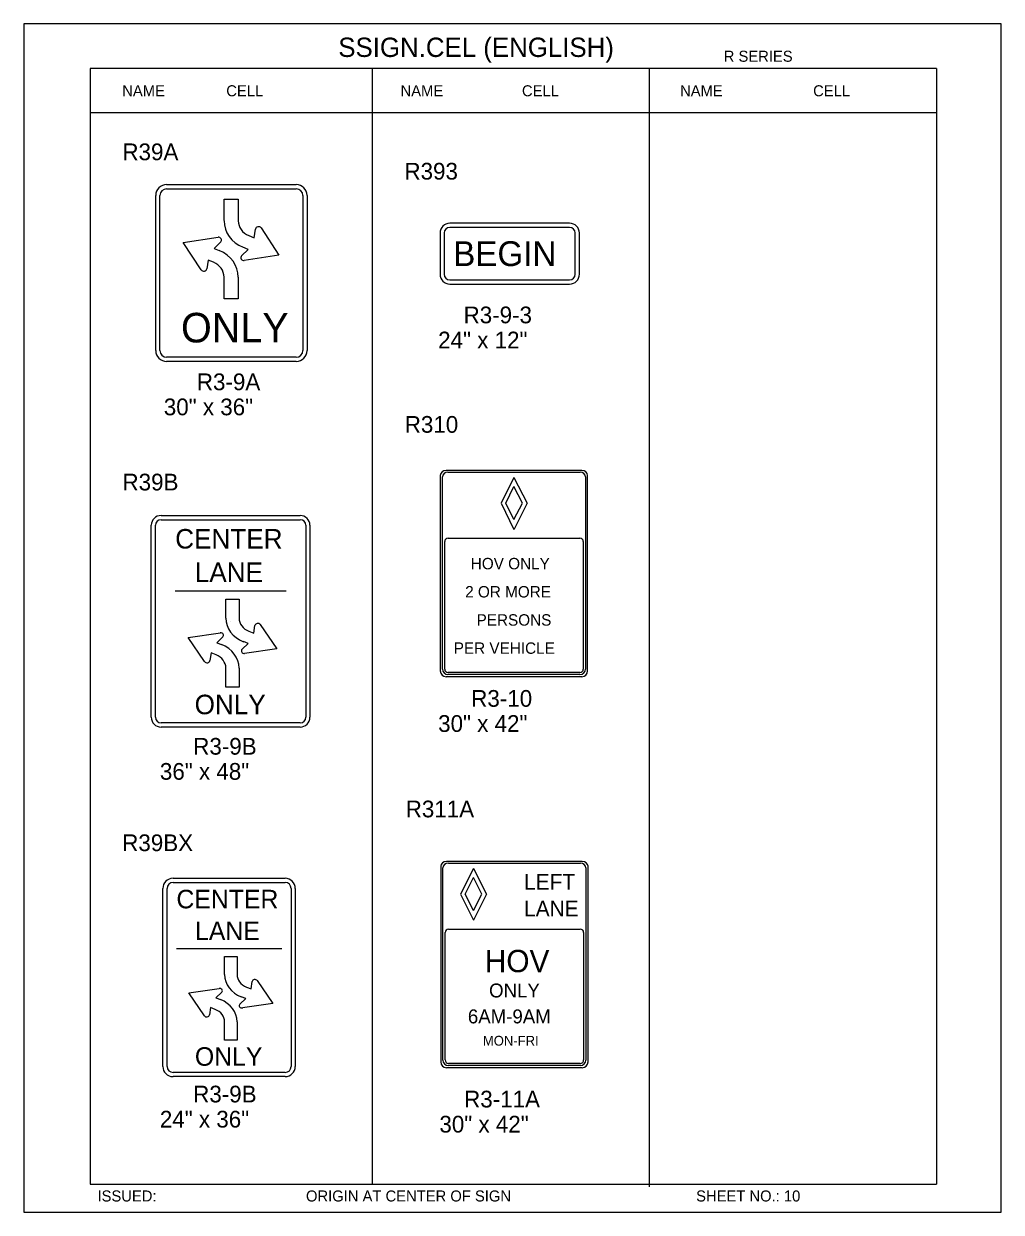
# Model space of a CAD drawing. Extents: x -5299 to 22597, y -19549 to -1808.
# Drawn here: x -2827 to -2126, y -4545 to -3692 of the extents above; entities that cross this region are included whole.
import ezdxf

# ---------------------------------------------------------------- set-up
doc = ezdxf.new("R2010")
doc.units = 0
for name, color, linetype in [('Level 1', 7, 'Continuous'), ('Level 2', 7, 'Continuous'), ('Level 3', 7, 'Continuous'), ('Level 63', 7, 'Continuous')]:
    doc.layers.add(name, color=color, linetype=linetype)

msp = doc.modelspace()

# ---------------------------------------------------------------- linework, layer by layer
at = {"layer": 'Level 1'}
for p, q in [((-2172.62, -3724.36), (-2779.63, -3724.36)), ((-2779.63, -3724.36), (-2779.63, -4524.36)), ((-2577.29, -3724.36), (-2577.29, -4524.36)), ((-2378.55, -3724.36), (-2378.55, -4524.36)), ((-2172.62, -3724.36), (-2172.62, -4524.36)), ((-2378.55, -3726.39), (-2378.55, -4526.39)), ((-2172.62, -3756.03), (-2779.63, -3756.03)), ((-2729.49, -3926.55), (-2729.49, -3815.35)), ((-2724.69, -3810.55), (-2631.77, -3810.55)), ((-2683.49, -3833.38), (-2683.49, -3817.93)), ((-2683.49, -3817.93), (-2673.31, -3817.93)), ((-2673.31, -3817.93), (-2673.31, -3833.44)), ((-2626.97, -3815.35), (-2626.97, -3926.55)), ((-2665.74, -3844.1), (-2661.9, -3845.68)), ((-2661.9, -3845.68), (-2660.98, -3839.41)), ((-2656.87, -3838.59), (-2644.09, -3858.2)), ((-2525.59, -3842.23), (-2525.59, -3871.85)), ((-2435.68, -3838.23), (-2521.59, -3838.23)), ((-2431.68, -3871.85), (-2431.68, -3842.23)), ((-2712.71, -3849.08), (-2687.79, -3845.27)), ((-2699.92, -3868.69), (-2712.71, -3849.08)), ((-2685.83, -3848.61), (-2690.6, -3853.29)), ((-2666.2, -3853.99), (-2669.92, -3852.47)), ((-2690.6, -3853.29), (-2686.88, -3854.81)), ((-2670.96, -3858.67), (-2666.2, -3853.99)), ((-2644.09, -3858.2), (-2669.01, -3862.01)), ((-2478.63, -3857.04), (-2478.63, -3857.04)), ((-2694.9, -3861.6), (-2695.81, -3867.87)), ((-2691.05, -3863.18), (-2694.9, -3861.6)), ((-2683.49, -3889.35), (-2683.49, -3873.84)), ((-2678.23, -3870.95), (-2678.23, -3870.95)), ((-2673.31, -3873.89), (-2673.31, -3889.35)), ((-2521.59, -3875.85), (-2435.68, -3875.85)), ((-2673.31, -3889.35), (-2683.49, -3889.35)), ((-2631.77, -3931.35), (-2724.69, -3931.35)), ((-2522.9, -4013.86), (-2428.2, -4013.86)), ((-2526.81, -4155), (-2526.81, -4017.07)), ((-2424.29, -4017.07), (-2424.29, -4155)), ((-2728.68, -4047.84), (-2628.88, -4047.84)), ((-2732.68, -4189.57), (-2732.68, -4051.84)), ((-2624.88, -4051.84), (-2624.88, -4189.57)), ((-2525.24, -4154.96), (-2525.24, -4063.57)), ((-2522.84, -4061.17), (-2428.26, -4061.17)), ((-2425.86, -4063.57), (-2425.86, -4154.96)), ((-2475.55, -4073.37), (-2475.55, -4073.37)), ((-2475.55, -4073.37), (-2475.55, -4073.37)), ((-2718.58, -4098.91), (-2639.01, -4098.91)), ((-2682.17, -4118.45), (-2682.17, -4104.78)), ((-2682.17, -4104.78), (-2672.75, -4104.78)), ((-2672.75, -4104.78), (-2672.75, -4118.5)), ((-2678.78, -4120.71), (-2678.78, -4120.71)), ((-2662.18, -4129.32), (-2661.34, -4123.78)), ((-2657.53, -4123.05), (-2645.69, -4140.4)), ((-2709.23, -4132.32), (-2686.16, -4128.96)), ((-2697.4, -4149.66), (-2709.23, -4132.32)), ((-2684.35, -4131.91), (-2688.76, -4136.05)), ((-2665.75, -4127.92), (-2662.18, -4129.32)), ((-2688.76, -4136.05), (-2685.32, -4137.4)), ((-2670.58, -4140.81), (-2666.17, -4136.67)), ((-2666.17, -4136.67), (-2669.61, -4135.32)), ((-2645.69, -4140.4), (-2668.76, -4143.76)), ((-2692.74, -4143.4), (-2693.59, -4148.94)), ((-2689.18, -4144.8), (-2692.74, -4143.4)), ((-2682.17, -4167.94), (-2682.17, -4154.22)), ((-2672.75, -4154.27), (-2672.75, -4167.94)), ((-2428.21, -4158.92), (-2522.89, -4158.92)), ((-2428.26, -4157.36), (-2522.84, -4157.36)), ((-2672.75, -4167.94), (-2682.17, -4167.94)), ((-2628.88, -4193.57), (-2728.68, -4193.57)), ((-2522.63, -4294.26), (-2427.92, -4294.26)), ((-2526.54, -4435.41), (-2526.54, -4297.48)), ((-2424.01, -4297.48), (-2424.01, -4435.41)), ((-2724.41, -4439.97), (-2724.41, -4312.35)), ((-2720.09, -4308.03), (-2639.7, -4308.03)), ((-2635.38, -4312.35), (-2635.38, -4439.97)), ((-2524.97, -4435.36), (-2524.97, -4343.98)), ((-2522.57, -4341.58), (-2427.98, -4341.58)), ((-2425.58, -4343.98), (-2425.58, -4435.36)), ((-2717.7, -4355.46), (-2642.11, -4355.46)), ((-2683.12, -4374.02), (-2683.12, -4361.03)), ((-2683.12, -4361.03), (-2674.16, -4361.03)), ((-2674.16, -4361.03), (-2674.16, -4374.07)), ((-2475.27, -4366.94), (-2475.27, -4366.94)), ((-2679.89, -4376.16), (-2679.89, -4376.16)), ((-2664.12, -4384.34), (-2663.32, -4379.08)), ((-2659.7, -4378.39), (-2648.46, -4394.87)), ((-2708.82, -4387.2), (-2686.9, -4384)), ((-2697.58, -4403.67), (-2708.82, -4387.2)), ((-2685.18, -4386.81), (-2689.37, -4390.74)), ((-2667.51, -4383.02), (-2664.12, -4384.34)), ((-2693.16, -4397.72), (-2693.96, -4402.99)), ((-2689.77, -4399.05), (-2693.16, -4397.72)), ((-2689.37, -4390.74), (-2686.1, -4392.02)), ((-2672.1, -4395.26), (-2667.91, -4391.33)), ((-2667.91, -4391.33), (-2671.18, -4390.05)), ((-2648.46, -4394.87), (-2670.38, -4398.06)), ((-2683.12, -4421.03), (-2683.12, -4408)), ((-2674.16, -4408.05), (-2674.16, -4421.03)), ((-2674.16, -4421.03), (-2683.12, -4421.03)), ((-2427.93, -4439.33), (-2522.62, -4439.33)), ((-2427.98, -4437.76), (-2522.57, -4437.76)), ((-2639.7, -4444.29), (-2720.09, -4444.29)), ((-2779.63, -4524.36), (-2172.62, -4524.36))]:
    msp.add_line(p, q, dxfattribs=at)
for centre, radius, start, end in [((-2724.69, -3815.35), 4.8, 90, 180), ((-2631.77, -3815.35), 4.8, 0, 90), ((-2521.59, -3842.23), 4, 90, 180), ((-2435.68, -3842.23), 4, 0, 90), ((-2521.59, -3871.85), 4, 180, 270), ((-2435.68, -3871.85), 4, 270, 0), ((-2724.69, -3926.55), 4.8, 180, 270), ((-2631.77, -3926.55), 4.8, 270, 0), ((-2728.68, -4051.84), 4, 90, 180), ((-2628.88, -4051.84), 4, 0, 90), ((-2522.84, -4063.57), 2.4, 90, 180), ((-2428.26, -4063.57), 2.4, 0, 90), ((-2522.89, -4155), 3.92, 180, 270), ((-2522.84, -4154.96), 2.4, 180, 270), ((-2428.26, -4154.96), 2.4, 270, 0), ((-2428.21, -4155), 3.92, 270, 0), ((-2728.68, -4189.57), 4, 180, 270), ((-2628.88, -4189.57), 4, 270, 0), ((-2720.09, -4312.35), 4.32, 90, 180), ((-2639.7, -4312.35), 4.32, 0, 90), ((-2522.57, -4343.98), 2.4, 90, 180), ((-2427.98, -4343.98), 2.4, 0, 90), ((-2720.09, -4439.97), 4.32, 180, 270), ((-2639.7, -4439.97), 4.32, 270, 0), ((-2522.62, -4435.41), 3.92, 180, 270), ((-2522.57, -4435.36), 2.4, 180, 270), ((-2427.98, -4435.36), 2.4, 270, 0), ((-2427.93, -4435.41), 3.92, 270, 0)]:
    msp.add_arc(centre, radius, start, end, dxfattribs=at)
for centre, major_axis, ratio, start_param, end_param in [((-2660.13, -3833.42), (-23.38, 0), 0.8975, 6.282849, 7.423415), ((-2660.1, -3833.39), (13.19, 0), 0.8975, 3.143205, 4.271453), ((-2658.74, -3839.73), (-2.26, 0), 0.8975, 3.720842, 6.1394), ((-2687.54, -3847.26), (2.25, 0), 0.8975, 5.561964, 7.978205), ((-2696.67, -3873.86), (23.38, 0), 0.8975, 6.282849, 7.423415), ((-2669.26, -3860.02), (-2.25, 0), 0.8975, 5.561964, 7.978205), ((-2698.05, -3867.55), (2.26, 0), 0.8975, 3.720842, 6.1394), ((-2696.7, -3873.89), (-13.19, 0), 0.8975, 3.143205, 4.271453), ((-2522.9, -4017.07), (-3.91, 0), 0.822115, 4.712389, 6.283185), ((-2428.2, -4017.07), (-3.91, 0), 0.822115, 3.141593, 4.712389), ((-2660.55, -4118.48), (-21.65, 0), 0.857082, 6.282849, 7.423415), ((-2660.52, -4118.45), (12.21, 0), 0.857082, 3.143205, 4.271453), ((-2659.26, -4124.06), (-2.09, 0), 0.857082, 3.720842, 6.1394), ((-2685.93, -4130.72), (2.09, 0), 0.857082, 5.561964, 7.978205), ((-2694.38, -4154.24), (21.65, 0), 0.857082, 6.282849, 7.423415), ((-2669, -4142), (-2.09, 0), 0.857082, 5.561964, 7.978205), ((-2695.66, -4148.66), (2.09, 0), 0.857082, 3.720842, 6.1394), ((-2694.41, -4154.27), (-12.21, 0), 0.857082, 3.143205, 4.271453), ((-2522.63, -4297.48), (-3.91, 0), 0.822115, 4.712389, 6.283185), ((-2427.92, -4297.48), (-3.91, 0), 0.822115, 3.141593, 4.712389), ((-2662.57, -4374.04), (-20.57, 0), 0.857082, 6.282849, 7.423415), ((-2662.54, -4374.02), (11.6, 0), 0.857082, 3.143205, 4.271453), ((-2661.35, -4379.35), (-1.99, 0), 0.857082, 3.720842, 6.1394), ((-2686.68, -4385.67), (1.98, 0), 0.857082, 5.561964, 7.978205), ((-2694.71, -4408.02), (20.57, 0), 0.857082, 6.282849, 7.423415), ((-2670.6, -4396.39), (-1.98, 0), 0.857082, 5.561964, 7.978205), ((-2695.93, -4402.72), (1.99, 0), 0.857082, 3.720842, 6.1394), ((-2694.74, -4408.05), (-11.6, 0), 0.857082, 3.143205, 4.271453)]:
    msp.add_ellipse(centre, major_axis=major_axis, ratio=ratio, start_param=start_param, end_param=end_param, dxfattribs=at)
at = {"layer": 'Level 3'}
for p, q in [((-2724.69, -3807.55), (-2631.77, -3807.55)), ((-2732.49, -3926.55), (-2732.49, -3815.35)), ((-2623.97, -3815.35), (-2623.97, -3926.55)), ((-2435.68, -3835.23), (-2521.59, -3835.23)), ((-2528.59, -3842.23), (-2528.59, -3871.85)), ((-2428.68, -3871.85), (-2428.68, -3842.23)), ((-2521.59, -3878.85), (-2435.68, -3878.85)), ((-2631.77, -3934.35), (-2724.69, -3934.35)), ((-2426.95, -4012.57), (-2524.15, -4012.57)), ((-2528.38, -4016.04), (-2528.38, -4156.29)), ((-2475.55, -4017.6), (-2484.74, -4035.98)), ((-2475.55, -4017.6), (-2466.14, -4035.98)), ((-2422.72, -4156.29), (-2422.72, -4016.04)), ((-2481.45, -4035.98), (-2475.55, -4024.16)), ((-2469.42, -4035.98), (-2475.55, -4024.16)), ((-2484.74, -4035.98), (-2475.55, -4054.79)), ((-2475.55, -4047.79), (-2481.45, -4035.98)), ((-2475.55, -4047.79), (-2469.42, -4035.98)), ((-2466.12, -4036.01), (-2475.47, -4054.69)), ((-2728.68, -4044.84), (-2628.88, -4044.84)), ((-2735.68, -4189.57), (-2735.68, -4051.84)), ((-2621.88, -4051.84), (-2621.88, -4189.57)), ((-2426.92, -4160.49), (-2524.18, -4160.49)), ((-2628.88, -4196.57), (-2728.68, -4196.57)), ((-2426.67, -4292.97), (-2523.88, -4292.97)), ((-2528.1, -4296.45), (-2528.1, -4436.7)), ((-2504.64, -4298.01), (-2513.83, -4316.38)), ((-2504.64, -4298.01), (-2495.23, -4316.38)), ((-2422.44, -4436.7), (-2422.44, -4296.45)), ((-2727.41, -4439.97), (-2727.41, -4312.35)), ((-2720.09, -4305.03), (-2639.7, -4305.03)), ((-2632.38, -4312.35), (-2632.38, -4439.97)), ((-2510.54, -4316.38), (-2504.64, -4304.57)), ((-2498.52, -4316.38), (-2504.64, -4304.57)), ((-2513.83, -4316.38), (-2504.64, -4335.19)), ((-2504.64, -4328.19), (-2510.54, -4316.38)), ((-2504.64, -4328.19), (-2498.52, -4316.38)), ((-2495.22, -4316.42), (-2504.56, -4335.1)), ((-2639.7, -4447.29), (-2720.09, -4447.29)), ((-2426.64, -4440.9), (-2523.9, -4440.9))]:
    msp.add_line(p, q, dxfattribs=at)
for centre, radius, start, end in [((-2724.69, -3815.35), 7.8, 90, 180), ((-2631.77, -3815.35), 7.8, 0, 90), ((-2521.59, -3842.23), 7, 90, 180), ((-2435.68, -3842.23), 7, 0, 90), ((-2521.59, -3871.85), 7, 180, 270), ((-2435.68, -3871.85), 7, 270, 0), ((-2724.69, -3926.55), 7.8, 180, 270), ((-2631.77, -3926.55), 7.8, 270, 0), ((-2728.68, -4051.84), 7, 90, 180), ((-2628.88, -4051.84), 7, 0, 90), ((-2524.18, -4156.29), 4.2, 180, 270), ((-2426.92, -4156.29), 4.2, 270, 0), ((-2728.68, -4189.57), 7, 180, 270), ((-2628.88, -4189.57), 7, 270, 0), ((-2720.09, -4312.35), 7.32, 90, 180), ((-2639.7, -4312.35), 7.32, 0, 90), ((-2720.09, -4439.97), 7.32, 180, 270), ((-2639.7, -4439.97), 7.32, 270, 0), ((-2523.9, -4436.7), 4.2, 180, 270), ((-2426.64, -4436.7), 4.2, 270, 0)]:
    msp.add_arc(centre, radius, start, end, dxfattribs=at)
for centre, start_param, end_param in [((-2524.15, -4016.04), 4.712389, 6.283185), ((-2426.95, -4016.04), 3.141593, 4.712389), ((-2523.88, -4296.45), 4.712389, 6.283185), ((-2426.67, -4296.45), 3.141593, 4.712389)]:
    msp.add_ellipse(centre, major_axis=(-4.23, 0), ratio=0.822115, start_param=start_param, end_param=end_param, dxfattribs=at)
at = {"layer": 'Level 63'}
msp.add_lwpolyline([(-2827.14, -4544.55), (-2126.09, -4544.55), (-2126.09, -3692.17), (-2827.14, -3692.17)], close=True, dxfattribs=at)

# ---------------------------------------------------------------- texts
at = {"layer": 'Level 1'}
for s, height, p in [('BEGIN', 17.779, (-2519.14, -3865.93)), ('ONLY', 21.2, (-2714.35, -3920.71)), ('CENTER', 14, (-2718.53, -4068.54)), ('LANE', 14, (-2704.47, -4092.54)), ('HOV ONLY', 8.2, (-2506.54, -4083.45)), ('2 OR MORE', 8.2, (-2510.57, -4103.65)), ('PERSONS', 8.2, (-2502.37, -4123.85)), ('PER VEHICLE', 8.2, (-2518.77, -4144.05)), ('ONLY', 14, (-2704.58, -4187.38)), ('CENTER', 13.3, (-2717.65, -4326.6)), ('LANE', 13.3, (-2704.3, -4349.4)), ('HOV', 16, (-2496.5, -4372.38)), ('ONLY', 10, (-2493.42, -4390.5)), ('6AM-9AM', 10, (-2508.62, -4409.1)), ('MON-FRI', 7, (-2497.87, -4425.04)), ('ONLY', 13.3, (-2704.4, -4439.5))]:
    msp.add_text(s, height=height, dxfattribs=at).set_placement(p)
at = {"layer": 'Level 2'}
for s, p in [('R39A', (-2756.39, -3790.02)), ('R393', (-2554.12, -3803.91)), ('R310', (-2553.89, -3985.51)), ('R39B', (-2756.33, -4026.87)), ('R311A', (-2553.2, -4261.32)), ('R39BX', (-2756.53, -4285.57))]:
    msp.add_text(s, height=12, dxfattribs=at).set_placement(p)
at = {"layer": 'Level 3'}
for s, height, p in [('SSIGN.CEL (ENGLISH)', 13.8566, (-2601.56, -3715.97)), ('R SERIES', 7.918, (-2325.12, -3719.41)), ('NAME', 7.918, (-2756.52, -3744.19)), ('CELL', 7.918, (-2681.9, -3744.19)), ('NAME', 7.918, (-2556.91, -3744.19)), ('CELL', 7.918, (-2469.83, -3744.19)), ('NAME', 7.918, (-2356.42, -3744.19)), ('CELL', 7.918, (-2261, -3744.19)), ('R3-9-3', 12, (-2511.7, -3906.99)), ('24" x 12"', 12, (-2529.93, -3924.99)), ('R3-9A', 12, (-2702.99, -3954.97)), ('30" x 36"', 12, (-2726.7, -3972.97)), ('R3-10', 12, (-2506.22, -4182.04)), ('30" x 42"', 12, (-2529.94, -4200.04)), ('R3-9B', 12, (-2705.59, -4216.38)), ('36" x 48"', 12, (-2729.5, -4234.38)), ('LEFT', 11.2, (-2468.3, -4313.14)), ('LANE', 11.2, (-2468.3, -4332.34)), ('R3-9B', 12, (-2705.64, -4465.8)), ('R3-11A', 12, (-2511.32, -4469.4)), ('24" x 36"', 12, (-2729.54, -4483.8)), ('30" x 42"', 12, (-2529.04, -4487.4)), ('ISSUED:', 7.918, (-2774.27, -4536.85)), ('ORIGIN AT CENTER OF SIGN', 7.9181, (-2624.73, -4536.85)), ('SHEET NO.: 10', 7.918, (-2344.92, -4536.85))]:
    msp.add_text(s, height=height, dxfattribs=at).set_placement(p)

doc.saveas('drawing.dxf')
